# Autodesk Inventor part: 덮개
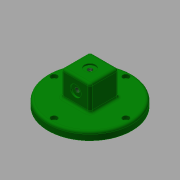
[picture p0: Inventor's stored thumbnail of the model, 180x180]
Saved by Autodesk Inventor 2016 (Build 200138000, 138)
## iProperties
Created: 2017-08
Part Number: 덮개
Material: 알루미늄 6061
Document SubType Name: Modeling
Designer: mduedu
Density: 1 g/cm^3
Appearance: 진녹색
Author: mduedu
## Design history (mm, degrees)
sketch "스케치1"
  geometry: C1 r 52.5 at (0, 0); 1 further point
  constraints: 1 centre point, 1 coincident
  dimensions: "d55" = 105 diameter of C1
extrude "돌출1" new body sketch "스케치1" distance "d5" = 10; taper "d6" = 0 deg
sketch "스케치2"
  geometry: L1 (-18, -18)-(18, -18); L2 (18, -18)-(18, 18); L3 (18, 18)-(-18, 18); L4 (-18, 18)-(-18, -18); L5 (-18, -18)-(18, 18); L6 (18, -18)-(-18, 18); 1 further point
  constraints: 12 end point, 2 midpoint, 2 parallel, 2 perpendicular, 1 horizontal
  dimensions: "d7" = 36 distance of L2.end L3.end
extrude "돌출2" join sketch "스케치2" distance "d9" = 32; taper "d10" = 0 deg
sketch "스케치3"
  geometry: C1 r 37 at (0, 0); 1 further point
  constraints: 1 centre point, 1 coincident
  dimensions: "d56" = 74 diameter of C1
extrude "돌출3" join sketch "스케치3" distance "d12" = 6; taper "d13" = 0 deg
sketch "스케치4"
  geometry: C1 r 33 at (0, 0); 1 further point
  constraints: 1 centre point, 1 coincident
  dimensions: "d57" = 66 diameter of C1
extrude "돌출4" cut sketch "스케치4" distance "d16" = 5; taper "d17" = 0 deg
sketch "스케치5"
  geometry: C1 r 9 at (0, 0); 1 further point
  constraints: 1 centre point, 1 coincident
  dimensions: "d18" = 18 diameter of C1
extrude "돌출5" cut sketch "스케치5" distance "d19" = 34; taper "d20" = 0 deg
sketch "스케치6"
  geometry: 2 further points
  constraints: 1 coincident
hole "구멍1" sketch "스케치6" at (0, 0) diameter "d21" = 5.917; stored, may be unused: countersink angle "d25" = 90 deg, drill point angle "d27" = 118 deg; dims "d22" = 6, "d23" = 14, "d24" = 2, "d26" = 8
sketch "스케치7"
  geometry: L1 (-34.5, -10)-(70.5, -10) reference; 3 further points
  constraints: 1 midpoint, 1 vertical alignment
  dimensions: "d58" = 26 distance from line of point (18, 16) L1
hole "구멍2" sketch "스케치7" at (18, 16) diameter "d29" = 5.917; stored, may be unused: countersink angle "d33" = 90 deg, drill point angle "d35" = 118 deg; dims "d30" = 6, "d31" = 14, "d32" = 2, "d34" = 8
fillet "모깎기2" dims "d37" = 3
fillet "모깎기3" dims "d38" = 3
fillet "모깎기4" dims "d39" = 3
fillet "모깎기5" dims "d40" = 3
chamfer "모따기1" distance "d41" = 1; stored, may be unused: second distance "d42" = 2, angle "d43" = 45 deg
fillet "모깎기7" dims "d45" = 3
fillet "모깎기8" dims "d46" = 3
sketch "스케치10" dims "d59" = 90
  geometry: 3 further points
  constraints: 2 vertical alignment, 1 coincident, 2 other
hole "구멍4" sketch "스케치10" at (0, 45) diameter "d60" = 4.5; stored, may be unused: countersink angle "d64" = 90 deg, drill point angle "d66" = 118 deg; dims "d61" = 6, "d62" = 8, "d63" = 4.6, "d65" = 8
node "솔리드1"
pattern_circular "원형 패턴1" dims angle "d68" = 360 deg
